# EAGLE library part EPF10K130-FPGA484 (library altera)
EPF10K130 FLEX 10K family
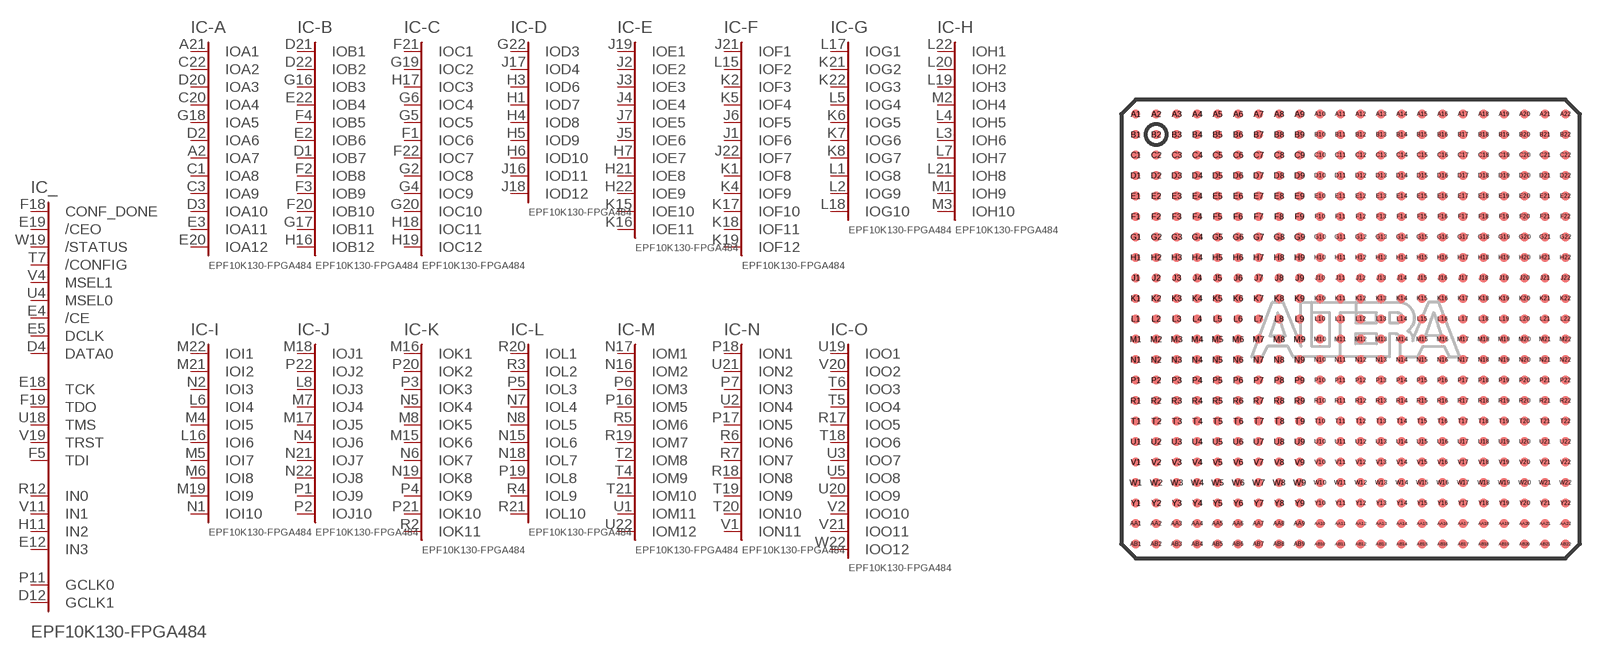
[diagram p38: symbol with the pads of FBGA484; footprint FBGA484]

Designator prefix IC; gates _=130E484C -A=A12-484 -B=B12-484 -C=C12-484 -D=D12-484 -E=E11-484 -F=F12-484 -G=G10-484 -H=H10-484 -I=I10-484 -J=J10-484 -K=K11-484 -L=L10-484 -M=M12-484 -N=N11-484 -O=O12-484 -P=P12-484 -1=51-484 -2=93-484 -3=141-484 -4=181-484 -5=222-484 -6=263-484 -7=311-484 -8=354-484 -9=403-484 -10=451-484 -11=493-484 -12=524-484 1=VCCINT 2=VCCINT 3=VCCINT 4=VCCINT 5=VCCINT 6=VCCINT 7=VCCINT 8=VCCINT 9=VCCINT 10=VCCINT 11=VCCINT 12=VCCINT 13=VCCINT 14=VCCINT 15=VCCINT 16=VCCINT 17=VCCINT 18=VCCINT 19=VCCINT 20=VCCINT 21=VCCINT 22=VCCINT 23=VCCINT 24=VCCIO 25=VCCIO 26=VCCIO 27=VCCIO 28=VCCIO 29=VCCIO 30=VCCIO 31=VCCIO 32=VCCIO 33=VCCIO 34=VCCIO 35=VCCIO 36=VCCIO 37=VCCIO 38=VCCIO 39=VCCIO 40=VCCIO 41=VCCIO 42=VCCIO 43=VCCIO 44=VCCIO 45=VCCIO 46=VCCIO 47=VCCIO 48=VCCIO 49=VCCIO 50=VCCIO 51=VCCIO 52=VCCIO 53=GND 54=GND 55=GND 56=GND 57=GND 58=GND 59=GND 60=GND 61=GND 62=GND 63=GND 64=GND 65=GND 66=GND 67=GND 68=GND 69=GND 70=GND 71=GND 72=GND 73=GND 74=GND 75=GND 76=GND 77=GND 78=GND 79=GND 80=GND 81=GND 82=GND 83=GND 84=GND 85=GND 86=GND 87=GND 88=GND 89=GND 90=GND 91=GND 92=GND 93=GND 94=GND 95=GND 96=GND 97=GND 98=GND 99=GND 100=GND 101=GND

## EPF10K130-FPGA484 (MPN: EPF10K130EFC484-1; OC_FARNELL: unknown; OC_NEWARK: 51R8855)  [FBGA484]
A1  58:GND  pwr
A2  -A:IOA7
A3  -1:IO23
A4  -1:IO42
A5  -2:IO83
A6  25:VCCIO  pwr
A7  -3:IO103
A8  59:GND  pwr
A9  -5:IO182
A10  -5:IO212
A11  -6:IO252
A12  -7:IO274
A13  26:VCCIO  pwr
A14  -8:IO322
A15  -9:IO362
A16  -9:IO391
A17  -10:IO422
A18  -11:IO463
A19  -11:IO471
A20  -12:IO513
A21  -A:IOA1
A22  60:GND  pwr
AA1  53:GND  pwr
AA2  -1:IO22
AA3  -1:IO21
AA4  -1:IO32
AA5  -2:IO61
AA6  54:GND  pwr
AA7  -4:IO144
AA8  -4:IO164
AA9  -5:IO191
AA10  -6:IO234
AA11  -7:IO264
AA12  1:VCC  pwr
AA13  -7:IO291
AA14  -8:IO342
AA15  -9:IO372
AA16  -9:IO402
AA17  -10:IO431
AA18  -11:IO461
AA19  -11:IO491
AA20  -12:IO511
AA21  -P:IOP6
AA22  55:GND  pwr
AB1  -1:IO11
AB2  -1:IO31
AB3  -1:IO41
AB4  -1:IO51
AB5  -2:IO82
AB6  -3:IO121
AB7  -3:IO141
AB8  -4:IO172
AB9  -5:IO201
AB10  -6:IO231
AB11  56:GND  pwr
AB12  -7:IO272
AB13  24:VCCIO  pwr
AB14  -8:IO321
AB15  -9:IO364
AB16  57:GND  pwr
AB17  -10:IO412
AB18  -10:IO442
AB19  -11:IO472
AB20  -12:IO503
AB21  -12:IO523
AB22  -P:IOP7
B1  61:GND  pwr
B2  62:GND  pwr
B3  -1:IO12
B4  -1:IO24
B5  27:VCCIO  pwr
B6  -2:IO72
B7  -3:IO122
B8  -4:IO153
B9  -5:IO192
B10  -5:IO222
B11  -6:IO262
B12  -7:IO282
B13  -7:IO293
B14  -8:IO333
B15  -9:IO371
B16  -9:IO403
B17  63:GND  pwr
B18  -11:IO462
B19  -11:IO493
B20  -12:IO524
B21  64:GND  pwr
B22  65:GND  pwr
C1  -A:IOA8
C2  66:GND  pwr
C3  -A:IOA9
C4  -1:IO13
C5  -2:IO52
C6  -2:IO73
C7  -2:IO93
C8  -3:IO133
C9  -4:IO173
C10  -5:IO221
C11  2:VCC  pwr
C12  -7:IO283
C13  -8:IO312
C14  -8:IO352
C15  3:VCC  pwr
C16  -10:IO433
C17  -11:IO453
C18  -11:IO482
C19  -12:IO501
C20  -A:IOA4
C21  67:GND  pwr
C22  -A:IOA2
D1  -B:IOB7
D2  -A:IOA6
D3  -A:IOA10
D4  _:DATA0  in
D5  -3:IO102
D6  -2:IO62
D7  -3:IO132
D8  -4:IO142
D9  -4:IO171
D10  -5:IO213
D11  -6:IO253
D12  _:GCLK1  in
D13  -7:IO302
D14  -9:IO373
D15  -10:IO413
D16  -10:IO423
D17  -11:IO473
D18  -12:IO512
D19  -12:IO522
D20  -A:IOA3
D21  -B:IOB1
D22  -B:IOB2
E1  28:VCCIO  pwr
E2  -B:IOB6
E3  -A:IOA11
E4  _:/CE  in
E5  _:DCLK  in
E6  -2:IO92
E7  -3:IO123
E8  -4:IO152
E9  -4:IO163
E10  -6:IO232
E11  -6:IO242
E12  _:IN3  in
E13  -8:IO313
E14  -9:IO383
E15  -10:IO432
E16  -10:IO441
E17  -12:IO502
E18  _:TCK
E19  _:/CEO  in
E20  -A:IOA12
E21  68:GND  pwr
E22  -B:IOB4
F1  -C:IOC6
F2  -B:IOB8
F3  -B:IOB9
F4  -B:IOB5
F5  _:TDI
F6  -3:IO112
F7  -1:IO33
F8  -2:IO84
F9  -4:IO162
F10  -5:IO193
F11  -6:IO233
F12  -7:IO273
F13  -8:IO343
F14  -9:IO382
F15  -10:IO443
F16  -11:IO452
F17  -11:IO492
F18  _:CONF_DONE  in
F19  _:TDO
F20  -B:IOB10
F21  -C:IOC1
F22  -C:IOC7
G1  29:VCCIO  pwr
G2  -C:IOC8
G3  69:GND  pwr
G4  -C:IOC9
G5  -C:IOC5
G6  -C:IOC4
G7  -4:IO143
G8  -1:IO34
G9  -2:IO53
G10  -5:IO203
G11  -6:IO263
G12  -6:IO243
G13  -8:IO353
G14  -10:IO411
G15  30:VCCIO  pwr
G16  -B:IOB3
G17  -B:IOB11
G18  -A:IOA5
G19  -C:IOC2
G20  -C:IOC10
G21  70:GND  pwr
G22  -D:IOD3
H1  -D:IOD7
H2  71:GND  pwr
H3  -D:IOD6
H4  -D:IOD8
H5  -D:IOD9
H6  -D:IOD10
H7  -E:IOE7
H8  72:GND  pwr
H9  31:VCCIO  pwr
H10  -5:IO183
H11  _:IN2  in
H12  -5:IO202
H13  -9:IO363
H14  4:VCC  pwr
H15  73:GND  pwr
H16  -B:IOB12
H17  -C:IOC3
H18  -C:IOC11
H19  -C:IOC12
H20  32:VCCIO  pwr
H21  -E:IOE8
H22  -E:IOE9
J1  -F:IOF6
J2  -E:IOE2
J3  -E:IOE3
J4  -E:IOE4
J5  -E:IOE6
J6  -F:IOF5
J7  -E:IOE5
J8  5:VCC  pwr
J9  74:GND  pwr
J10  6:VCC  pwr
J11  33:VCCIO  pwr
J12  7:VCC  pwr
J13  34:VCCIO  pwr
J14  75:GND  pwr
J15  8:VCC  pwr
J16  -D:IOD11
J17  -D:IOD4
J18  -D:IOD12
J19  -E:IOE1
J20  76:GND  pwr
J21  -F:IOF1
J22  -F:IOF7
K1  -F:IOF8
K2  -F:IOF3
K3  77:GND  pwr
K4  -F:IOF9
K5  -F:IOF4
K6  -G:IOG5
K7  -G:IOG6
K8  -G:IOG7
K9  35:VCCIO  pwr
K10  78:GND  pwr
K11  36:VCCIO  pwr
K12  79:GND  pwr
K13  80:GND  pwr
K14  37:VCCIO  pwr
K15  -E:IOE10
K16  -E:IOE11
K17  -F:IOF10
K18  -F:IOF11
K19  -F:IOF12
K20  38:VCCIO  pwr
K21  -G:IOG2
K22  -G:IOG3
L1  -G:IOG8
L2  -G:IOG9
L3  -H:IOH6
L4  -H:IOH5
L5  -G:IOG4
L6  -I:IOI4
L7  -H:IOH7
L8  -J:IOJ3
L9  9:VCC  pwr
L10  10:VCC  pwr
L11  81:GND  pwr
L12  82:GND  pwr
L13  11:VCC  pwr
L14  39:VCCIO  pwr
L15  -F:IOF2
L16  -I:IOI6
L17  -G:IOG1
L18  -G:IOG10
L19  -H:IOH3
L20  -H:IOH2
L21  -H:IOH8
L22  -H:IOH1
M1  -H:IOH9
M2  -H:IOH4
M3  -H:IOH10
M4  -I:IOI5
M5  -I:IOI7
M6  -I:IOI8
M7  -J:IOJ4
M8  -K:IOK5
M9  40:VCCIO  pwr
M10  12:VCC  pwr
M11  83:GND  pwr
M12  84:GND  pwr
M13  13:VCC  pwr
M14  14:VCC  pwr
M15  -K:IOK6
M16  -K:IOK1
M17  -J:IOJ5
M18  -J:IOJ1
M19  -I:IOI9
M20  85:GND  pwr
M21  -I:IOI2
M22  -I:IOI1
N1  -I:IOI10
N2  -I:IOI3
N3  41:VCCIO  pwr
N4  -J:IOJ6
N5  -K:IOK4
N6  -K:IOK7
N7  -L:IOL4
N8  -L:IOL5
N9  42:VCCIO  pwr
N10  86:GND  pwr
N11  43:VCCIO  pwr
N12  15:VCC  pwr
N13  87:GND  pwr
N14  44:VCCIO  pwr
N15  -L:IOL6
N16  -M:IOM2
N17  -M:IOM1
N18  -L:IOL7
N19  -K:IOK8
N20  45:VCCIO  pwr
N21  -J:IOJ7
N22  -J:IOJ8
P1  -J:IOJ9
P2  -J:IOJ10
P3  -K:IOK3
P4  -K:IOK9
P5  -L:IOL3
P6  -M:IOM3
P7  -N:ION3
P8  16:VCC  pwr
P9  88:GND  pwr
P10  17:VCC  pwr
P11  _:GCLK0  in
P12  18:VCC  pwr
P13  46:VCCIO  pwr
P14  89:GND  pwr
P15  19:VCC  pwr
P16  -M:IOM5
P17  -N:ION5
P18  -N:ION1
P19  -L:IOL8
P20  -K:IOK2
P21  -K:IOK10
P22  -J:IOJ2
R1  47:VCCIO  pwr
R2  -K:IOK11
R3  -L:IOL2
R4  -L:IOL9
R5  -M:IOM6
R6  -N:ION6
R7  -N:ION7
R8  90:GND  pwr
R9  48:VCCIO  pwr
R10  -4:IO151
R11  -6:IO244
R12  _:IN0  in
R13  -7:IO301
R14  20:VCC  pwr
R15  91:GND  pwr
R16  -P:IOP8
R17  -O:IOO5
R18  -N:ION8
R19  -M:IOM7
R20  -L:IOL1
R21  -L:IOL10
R22  92:GND  pwr
T1  93:GND  pwr
T2  -M:IOM8
T3  49:VCCIO  pwr
T4  -M:IOM9
T5  -O:IOO4
T6  -O:IOO3
T7  _:/CONFIG  in
T8  -3:IO111
T9  -4:IO154
T10  -5:IO204
T11  -6:IO241
T12  -7:IO303
T13  -8:IO331
T14  -10:IO421
T15  50:VCCIO  pwr
T16  -P:IOP9
T17  -P:IOP10
T18  -O:IOO6
T19  -N:ION9
T20  -N:ION10
T21  -M:IOM10
T22  51:VCCIO  pwr
U1  -M:IOM11
U2  -N:ION4
U3  -O:IOO7
U4  _:MSEL0  in
U5  -O:IOO8
U6  -P:IOP11
U7  -3:IO94
U8  -3:IO113
U9  -4:IO181
U10  -5:IO214
U11  -6:IO254
U12  -7:IO292
U13  -8:IO332
U14  -9:IO374
U15  -9:IO361
U16  -10:IO451
U17  -11:IO474
U18  _:TMS
U19  -O:IOO1
U20  -O:IOO9
U21  -N:ION2
U22  -M:IOM12
V1  -N:ION11
V2  -O:IOO10
V3  101:GND  pwr
V4  _:MSEL1  in
V5  21:VCC  pwr
V6  -2:IO74
V7  -2:IO91
V8  -3:IO124
V9  -4:IO174
V10  -5:IO211
V11  _:IN1  in
V12  -7:IO281
V13  -7:IO311
V14  -8:IO341
V15  -9:IO401
V16  -10:IO444
V17  -12:IO494
V18  -P:IOP2
V19  _:TRST
V20  -O:IOO2
V21  -O:IOO11
V22  52:VCCIO  pwr
W1  -P:IOP12
W2  -P:IOP5
W3  -P:IOP3
W4  -P:IOP4
W5  -1:IO43
W6  -2:IO71
W7  -3:IO101
W8  -3:IO131
W9  -4:IO161
W10  -6:IO223
W11  94:GND  pwr
W12  -7:IO271
W13  -8:IO323
W14  -8:IO351
W15  -9:IO392
W16  -10:IO434
W17  -11:IO483
W18  -12:IO504
W19  _:/STATUS  in
W20  95:GND  pwr
W21  22:VCC  pwr
W22  -O:IOO12
Y1  96:GND  pwr
Y2  97:GND  pwr
Y3  98:GND  pwr
Y4  -1:IO14
Y5  -2:IO63
Y6  -2:IO81
Y7  -3:IO104
Y8  23:VCC  pwr
Y9  -5:IO184
Y10  -6:IO224
Y11  -6:IO251
Y12  -7:IO284
Y13  -8:IO314
Y14  -8:IO354
Y15  -9:IO381
Y16  -10:IO414
Y17  -11:IO454
Y18  -11:IO481
Y19  -12:IO514
Y20  -12:IO521
Y21  99:GND  pwr
Y22  100:GND  pwr

## Footprint FBGA484 (pad centres in mm)
Fine Ball Grid Array
smd 0.45 x 0.45: A1 -10.5,10.5; A2 -9.5,10.5; A3 -8.5,10.5; A4 -7.5,10.5; A5 -6.5,10.5; A6 -5.5,10.5; A7 -4.5,10.5; A8 -3.5,10.5; A9 -2.5,10.5; A10 -1.5,10.5; A11 -0.5,10.5; A12 0.5,10.5; A13 1.5,10.5; A14 2.5,10.5; A15 3.5,10.5; A16 4.5,10.5; A17 5.5,10.5; A18 6.5,10.5; A19 7.5,10.5; A20 8.5,10.5; A21 9.5,10.5; A22 10.5,10.5; AA1 -10.5,-9.5; AA2 -9.5,-9.5; AA3 -8.5,-9.5; AA4 -7.5,-9.5; AA5 -6.5,-9.5; AA6 -5.5,-9.5; AA7 -4.5,-9.5; AA8 -3.5,-9.5; AA9 -2.5,-9.5; AA10 -1.5,-9.5; AA11 -0.5,-9.5; AA12 0.5,-9.5; AA13 1.5,-9.5; AA14 2.5,-9.5; AA15 3.5,-9.5; AA16 4.5,-9.5; AA17 5.5,-9.5; AA18 6.5,-9.5; AA19 7.5,-9.5; AA20 8.5,-9.5; AA21 9.5,-9.5; AA22 10.5,-9.5; AB1 -10.5,-10.5; AB2 -9.5,-10.5; AB3 -8.5,-10.5; AB4 -7.5,-10.5; AB5 -6.5,-10.5; AB6 -5.5,-10.5; AB7 -4.5,-10.5; AB8 -3.5,-10.5; AB9 -2.5,-10.5; AB10 -1.5,-10.5; AB11 -0.5,-10.5; AB12 0.5,-10.5; AB13 1.5,-10.5; AB14 2.5,-10.5; AB15 3.5,-10.5; AB16 4.5,-10.5; AB17 5.5,-10.5; AB18 6.5,-10.5; AB19 7.5,-10.5; AB20 8.5,-10.5; AB21 9.5,-10.5; AB22 10.5,-10.5; B1 -10.5,9.5; B2 -9.5,9.5; B3 -8.5,9.5; B4 -7.5,9.5; B5 -6.5,9.5; B6 -5.5,9.5; B7 -4.5,9.5; B8 -3.5,9.5; B9 -2.5,9.5; B10 -1.5,9.5; B11 -0.5,9.5; B12 0.5,9.5; B13 1.5,9.5; B14 2.5,9.5; B15 3.5,9.5; B16 4.5,9.5; B17 5.5,9.5; B18 6.5,9.5; B19 7.5,9.5; B20 8.5,9.5; B21 9.5,9.5; B22 10.5,9.5; C1 -10.5,8.5; C2 -9.5,8.5; C3 -8.5,8.5; C4 -7.5,8.5; C5 -6.5,8.5; C6 -5.5,8.5; C7 -4.5,8.5; C8 -3.5,8.5; C9 -2.5,8.5; C10 -1.5,8.5; C11 -0.5,8.5; C12 0.5,8.5; C13 1.5,8.5; C14 2.5,8.5; C15 3.5,8.5; C16 4.5,8.5; C17 5.5,8.5; C18 6.5,8.5; C19 7.5,8.5; C20 8.5,8.5; C21 9.5,8.5; C22 10.5,8.5; D1 -10.5,7.5; D2 -9.5,7.5; D3 -8.5,7.5; D4 -7.5,7.5; D5 -6.5,7.5; D6 -5.5,7.5; D7 -4.5,7.5; D8 -3.5,7.5; D9 -2.5,7.5; D10 -1.5,7.5; D11 -0.5,7.5; D12 0.5,7.5; D13 1.5,7.5; D14 2.5,7.5; D15 3.5,7.5; D16 4.5,7.5; D17 5.5,7.5; D18 6.5,7.5; D19 7.5,7.5; D20 8.5,7.5; D21 9.5,7.5; D22 10.5,7.5; E1 -10.5,6.5; E2 -9.5,6.5; E3 -8.5,6.5; E4 -7.5,6.5; E5 -6.5,6.5; E6 -5.5,6.5; E7 -4.5,6.5; E8 -3.5,6.5; E9 -2.5,6.5; E10 -1.5,6.5; E11 -0.5,6.5; E12 0.5,6.5; E13 1.5,6.5; E14 2.5,6.5; E15 3.5,6.5; E16 4.5,6.5; E17 5.5,6.5; E18 6.5,6.5; E19 7.5,6.5; E20 8.5,6.5; E21 9.5,6.5; E22 10.5,6.5; F1 -10.5,5.5; F2 -9.5,5.5; F3 -8.5,5.5; F4 -7.5,5.5; F5 -6.5,5.5; F6 -5.5,5.5; F7 -4.5,5.5; F8 -3.5,5.5; F9 -2.5,5.5; F10 -1.5,5.5; F11 -0.5,5.5; F12 0.5,5.5; F13 1.5,5.5; F14 2.5,5.5; F15 3.5,5.5; F16 4.5,5.5; F17 5.5,5.5; F18 6.5,5.5; F19 7.5,5.5; F20 8.5,5.5; F21 9.5,5.5; F22 10.5,5.5; G1 -10.5,4.5; G2 -9.5,4.5; G3 -8.5,4.5; G4 -7.5,4.5; G5 -6.5,4.5; G6 -5.5,4.5; G7 -4.5,4.5; G8 -3.5,4.5; G9 -2.5,4.5; G10 -1.5,4.5; G11 -0.5,4.5; G12 0.5,4.5; G13 1.5,4.5; G14 2.5,4.5; G15 3.5,4.5; G16 4.5,4.5; G17 5.5,4.5; G18 6.5,4.5; G19 7.5,4.5; G20 8.5,4.5; G21 9.5,4.5; G22 10.5,4.5; H1 -10.5,3.5; H2 -9.5,3.5; H3 -8.5,3.5; H4 -7.5,3.5; H5 -6.5,3.5; H6 -5.5,3.5; H7 -4.5,3.5; H8 -3.5,3.5; H9 -2.5,3.5; H10 -1.5,3.5; H11 -0.5,3.5; H12 0.5,3.5; H13 1.5,3.5; H14 2.5,3.5; H15 3.5,3.5; H16 4.5,3.5; H17 5.5,3.5; H18 6.5,3.5; H19 7.5,3.5; H20 8.5,3.5; H21 9.5,3.5; H22 10.5,3.5; J1 -10.5,2.5; J2 -9.5,2.5; J3 -8.5,2.5; J4 -7.5,2.5; J5 -6.5,2.5; J6 -5.5,2.5; J7 -4.5,2.5; J8 -3.5,2.5; J9 -2.5,2.5; J10 -1.5,2.5; J11 -0.5,2.5; J12 0.5,2.5; J13 1.5,2.5; J14 2.5,2.5; J15 3.5,2.5; J16 4.5,2.5; J17 5.5,2.5; J18 6.5,2.5; J19 7.5,2.5; J20 8.5,2.5; J21 9.5,2.5; J22 10.5,2.5; K1 -10.5,1.5; K2 -9.5,1.5; K3 -8.5,1.5; K4 -7.5,1.5; K5 -6.5,1.5; K6 -5.5,1.5; K7 -4.5,1.5; K8 -3.5,1.5; K9 -2.5,1.5; K10 -1.5,1.5; K11 -0.5,1.5; K12 0.5,1.5; K13 1.5,1.5; K14 2.5,1.5; K15 3.5,1.5; K16 4.5,1.5; K17 5.5,1.5; K18 6.5,1.5; K19 7.5,1.5; K20 8.5,1.5; K21 9.5,1.5; K22 10.5,1.5; L1 -10.5,0.5; L2 -9.5,0.5; L3 -8.5,0.5; L4 -7.5,0.5; L5 -6.5,0.5; L6 -5.5,0.5; L7 -4.5,0.5; L8 -3.5,0.5; L9 -2.5,0.5; L10 -1.5,0.5; L11 -0.5,0.5; L12 0.5,0.5; L13 1.5,0.5; L14 2.5,0.5; L15 3.5,0.5; L16 4.5,0.5; L17 5.5,0.5; L18 6.5,0.5; L19 7.5,0.5; L20 8.5,0.5; L21 9.5,0.5; L22 10.5,0.5; M1 -10.5,-0.5; M2 -9.5,-0.5; M3 -8.5,-0.5; M4 -7.5,-0.5; M5 -6.5,-0.5; M6 -5.5,-0.5; M7 -4.5,-0.5; M8 -3.5,-0.5; M9 -2.5,-0.5; M10 -1.5,-0.5; M11 -0.5,-0.5; M12 0.5,-0.5; M13 1.5,-0.5; M14 2.5,-0.5; M15 3.5,-0.5; M16 4.5,-0.5; M17 5.5,-0.5; M18 6.5,-0.5; M19 7.5,-0.5; M20 8.5,-0.5; M21 9.5,-0.5; M22 10.5,-0.5; N1 -10.5,-1.5; N2 -9.5,-1.5; N3 -8.5,-1.5; N4 -7.5,-1.5; N5 -6.5,-1.5; N6 -5.5,-1.5; N7 -4.5,-1.5; N8 -3.5,-1.5; N9 -2.5,-1.5; N10 -1.5,-1.5; N11 -0.5,-1.5; N12 0.5,-1.5; N13 1.5,-1.5; N14 2.5,-1.5; N15 3.5,-1.5; N16 4.5,-1.5; N17 5.5,-1.5; N18 6.5,-1.5; N19 7.5,-1.5; N20 8.5,-1.5; N21 9.5,-1.5; N22 10.5,-1.5; P1 -10.5,-2.5; P2 -9.5,-2.5; P3 -8.5,-2.5; P4 -7.5,-2.5; P5 -6.5,-2.5; P6 -5.5,-2.5; P7 -4.5,-2.5; P8 -3.5,-2.5; P9 -2.5,-2.5; P10 -1.5,-2.5; P11 -0.5,-2.5; P12 0.5,-2.5; P13 1.5,-2.5; P14 2.5,-2.5; P15 3.5,-2.5; P16 4.5,-2.5; P17 5.5,-2.5; P18 6.5,-2.5; P19 7.5,-2.5; P20 8.5,-2.5; P21 9.5,-2.5; P22 10.5,-2.5; R1 -10.5,-3.5; R2 -9.5,-3.5; R3 -8.5,-3.5; R4 -7.5,-3.5; R5 -6.5,-3.5; R6 -5.5,-3.5; R7 -4.5,-3.5; R8 -3.5,-3.5; R9 -2.5,-3.5; R10 -1.5,-3.5; R11 -0.5,-3.5; R12 0.5,-3.5; R13 1.5,-3.5; R14 2.5,-3.5; R15 3.5,-3.5; R16 4.5,-3.5; R17 5.5,-3.5; R18 6.5,-3.5; R19 7.5,-3.5; R20 8.5,-3.5; R21 9.5,-3.5; R22 10.5,-3.5; T1 -10.5,-4.5; T2 -9.5,-4.5; T3 -8.5,-4.5; T4 -7.5,-4.5; T5 -6.5,-4.5; T6 -5.5,-4.5; T7 -4.5,-4.5; T8 -3.5,-4.5; T9 -2.5,-4.5; T10 -1.5,-4.5; T11 -0.5,-4.5; T12 0.5,-4.5; T13 1.5,-4.5; T14 2.5,-4.5; T15 3.5,-4.5; T16 4.5,-4.5; T17 5.5,-4.5; T18 6.5,-4.5; T19 7.5,-4.5; T20 8.5,-4.5; T21 9.5,-4.5; T22 10.5,-4.5; U1 -10.5,-5.5; U2 -9.5,-5.5; U3 -8.5,-5.5; U4 -7.5,-5.5; U5 -6.5,-5.5; U6 -5.5,-5.5; U7 -4.5,-5.5; U8 -3.5,-5.5; U9 -2.5,-5.5; U10 -1.5,-5.5; U11 -0.5,-5.5; U12 0.5,-5.5; U13 1.5,-5.5; U14 2.5,-5.5; U15 3.5,-5.5; U16 4.5,-5.5; U17 5.5,-5.5; U18 6.5,-5.5; U19 7.5,-5.5; U20 8.5,-5.5; U21 9.5,-5.5; U22 10.5,-5.5; V1 -10.5,-6.5; V2 -9.5,-6.5; V3 -8.5,-6.5; V4 -7.5,-6.5; V5 -6.5,-6.5; V6 -5.5,-6.5; V7 -4.5,-6.5; V8 -3.5,-6.5; V9 -2.5,-6.5; V10 -1.5,-6.5; V11 -0.5,-6.5; V12 0.5,-6.5; V13 1.5,-6.5; V14 2.5,-6.5; V15 3.5,-6.5; V16 4.5,-6.5; V17 5.5,-6.5; V18 6.5,-6.5; V19 7.5,-6.5; V20 8.5,-6.5; V21 9.5,-6.5; V22 10.5,-6.5; W1 -10.5,-7.5; W2 -9.5,-7.5; W3 -8.5,-7.5; W4 -7.5,-7.5; W5 -6.5,-7.5; W6 -5.5,-7.5; W7 -4.5,-7.5; W8 -3.5,-7.5; W9 -2.5,-7.5; W10 -1.5,-7.5; W11 -0.5,-7.5; W12 0.5,-7.5; W13 1.5,-7.5; W14 2.5,-7.5; W15 3.5,-7.5; W16 4.5,-7.5; W17 5.5,-7.5; W18 6.5,-7.5; W19 7.5,-7.5; W20 8.5,-7.5; W21 9.5,-7.5; W22 10.5,-7.5; Y1 -10.5,-8.5; Y2 -9.5,-8.5; Y3 -8.5,-8.5; Y4 -7.5,-8.5; Y5 -6.5,-8.5; Y6 -5.5,-8.5; Y7 -4.5,-8.5; Y8 -3.5,-8.5; Y9 -2.5,-8.5; Y10 -1.5,-8.5; Y11 -0.5,-8.5; Y12 0.5,-8.5; Y13 1.5,-8.5; Y14 2.5,-8.5; Y15 3.5,-8.5; Y16 4.5,-8.5; Y17 5.5,-8.5; Y18 6.5,-8.5; Y19 7.5,-8.5; Y20 8.5,-8.5; Y21 9.5,-8.5; Y22 10.5,-8.5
